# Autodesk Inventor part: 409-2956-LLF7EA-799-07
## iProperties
Created: 2010-11
Part Number: 409-2956-LLF7EA-799-07
Material: 3/4" OD TUBE - SS
Document SubType Name: Modeling
Designer: S. Boerckel
Engineer: Steve Boerckel
Density: 8.08 g/cm^3
Description: DRAIN TUBING
Mass: 332.362 g
Surface Area: 500.097 cm^2
Volume: 41.134 cm^3
Length: 17.945 in
Author: S. Boerckel
Revision Number: 0
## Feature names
1. TaggingFeature1
